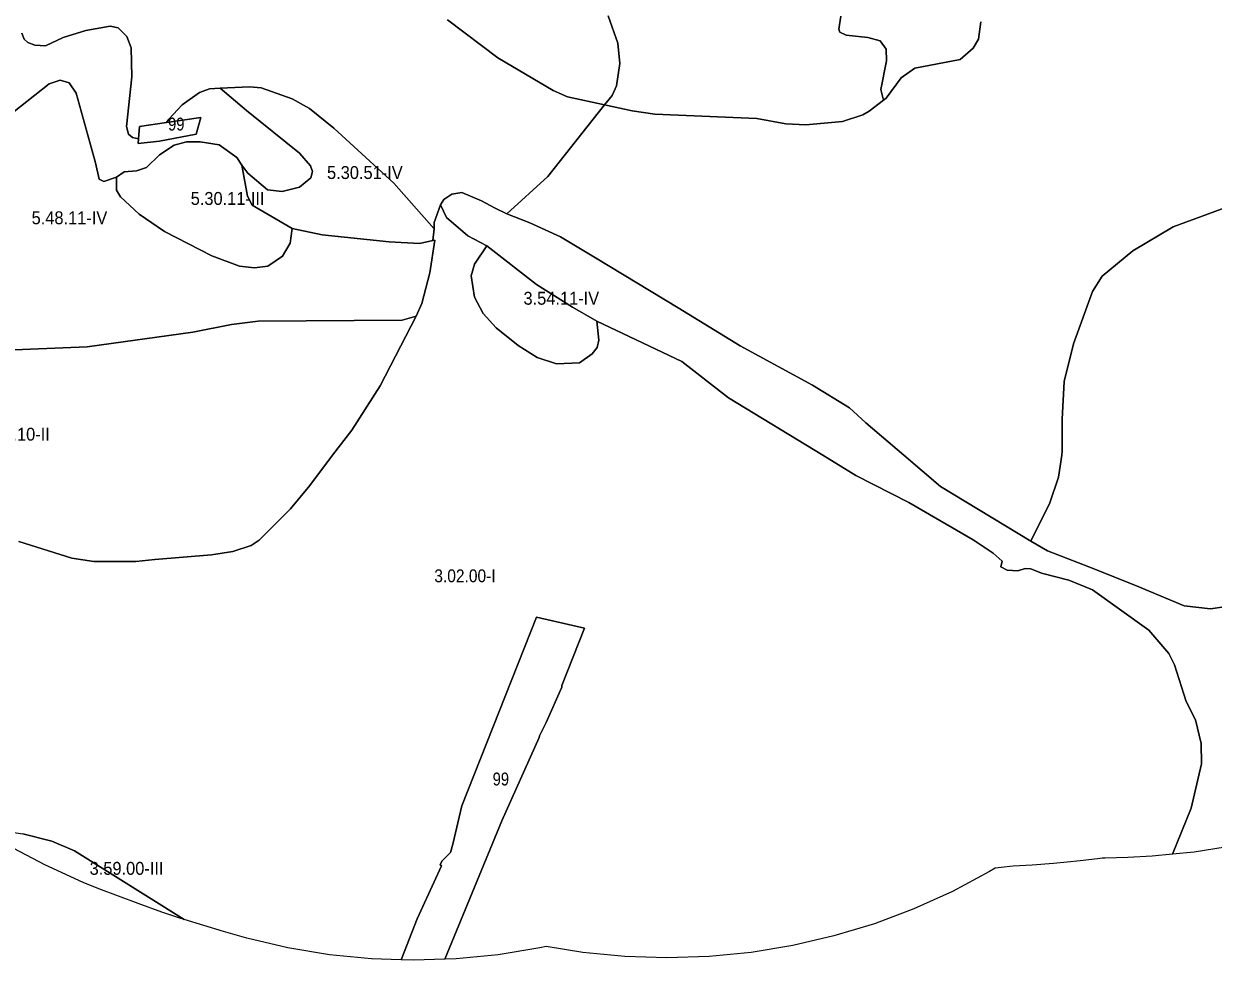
# Model space of a CAD drawing. Extents: x -591496 to -585489, y -1120610 to -1115685.
# Drawn here: x -589052 to -587209, y -1120610 to -1119158 of the extents above; entities that cross this region are included whole.
import ezdxf

# ---------------------------------------------------------------- set-up
doc = ezdxf.new("R2010")
doc.units = 0
doc.header["$LTSCALE"] = 8
doc.layers.add('40', color=7, linetype='Continuous', lineweight=25)
doc.layers.add('41', color=7, linetype='Continuous')

msp = doc.modelspace()

# ---------------------------------------------------------------- linework, layer by layer
at = {"layer": '40'}
for points in [[(-589054.5, -1119172.5), (-589051, -1119182), (-589045.5, -1119187), (-589034.5, -1119191), (-589018, -1119192), (-588990.5, -1119179.5), (-588955.5, -1119168.5), (-588917.5, -1119161.5), (-588905.5, -1119164.5), (-588892, -1119177.5), (-588885, -1119195.5), (-588884, -1119240.5), (-588892.5, -1119317), (-588889.5, -1119329), (-588883, -1119334.5), (-588873.972, -1119336.502), (-588874.5, -1119343.5), (-588841.5, -1119340), (-588784.5, -1119329), (-588777.5, -1119303.5), (-588830.496, -1119311.031), (-588827, -1119306), (-588806, -1119283.5), (-588779.5, -1119264.5), (-588764, -1119259), (-588747.5, -1119258), (-588706.5, -1119292.5), (-588624.5, -1119358.5), (-588607.5, -1119378), (-588604.5, -1119387), (-588607, -1119397), (-588624.5, -1119411.5), (-588651, -1119418), (-588674, -1119415.5), (-588704.5, -1119389.5), (-588713.5, -1119377), (-588721.5, -1119365.5), (-588749, -1119345.5), (-588778.5, -1119341), (-588799.5, -1119341), (-588818.5, -1119346), (-588841.5, -1119361), (-588861.5, -1119381), (-588877, -1119386), (-588896, -1119387.5), (-588908, -1119396), (-588927.5, -1119402.5), (-588935, -1119399), (-588940.5, -1119373.5), (-588952.5, -1119330.5), (-588970.5, -1119265.5), (-588981.5, -1119249.5), (-588995, -1119245.5), (-589012, -1119251), (-589079, -1119304)], [(-588395, -1119152), (-588317, -1119211), (-588231.5, -1119261.5), (-588209, -1119271.5), (-588151.702, -1119283.819), (-588239.5, -1119395), (-588303, -1119452.5), (-588322.5, -1119443.5), (-588342.5, -1119432.5), (-588373, -1119419.5), (-588388.5, -1119422), (-588401, -1119430.5), (-588406, -1119438.5), (-588416, -1119466), (-588416, -1119476), (-588478, -1119405), (-588571, -1119320), (-588609, -1119289.5), (-588635.5, -1119274.5), (-588684, -1119257.5), (-588702, -1119255.5), (-588747.5, -1119258), (-588764, -1119259), (-588779.5, -1119264.5), (-588806, -1119283.5), (-588827, -1119306), (-588830.496, -1119311.031), (-588872.5, -1119317), (-588873.972, -1119336.502), (-588883, -1119334.5), (-588889.5, -1119329), (-588892.5, -1119317), (-588884, -1119240.5), (-588885, -1119195.5), (-588892, -1119177.5), (-588905.5, -1119164.5), (-588917.5, -1119161.5), (-588955.5, -1119168.5), (-588990.5, -1119179.5), (-589018, -1119192), (-589034.5, -1119191), (-589045.5, -1119187), (-589051, -1119182), (-589054.5, -1119172.5)], [(-588146, -1119145.5), (-588131, -1119188), (-588128, -1119219.5), (-588133.5, -1119254), (-588140, -1119269), (-588151.702, -1119283.819), (-588209, -1119271.5), (-588231.5, -1119261.5), (-588317, -1119211), (-588395, -1119152)], [(-587171, -1119436), (-587271, -1119473), (-587333.5, -1119510), (-587381, -1119549), (-587396, -1119573), (-587425, -1119654), (-587439.5, -1119712.5), (-587442.5, -1119771), (-587442.5, -1119820.5), (-587443.448, -1119826.9), (-587448.5, -1119861), (-587462, -1119900.5), (-587491.5, -1119960), (-587631, -1119875.5), (-587687.946, -1119826.9), (-587747, -1119776.5), (-587772.5, -1119753.5), (-587829.5, -1119718), (-587941.5, -1119657.5), (-588037.5, -1119598.5), (-588166, -1119521), (-588220, -1119488.5), (-588267.5, -1119466.5), (-588303, -1119452.5), (-588239.5, -1119395), (-588151.702, -1119283.819), (-588109, -1119293), (-588074, -1119298), (-587916, -1119305), (-587871, -1119313), (-587840, -1119314.5), (-587783, -1119309.5), (-587751.5, -1119299), (-587742, -1119293.5), (-587719.491, -1119276.512), (-587715.5, -1119273.5), (-587692, -1119242), (-587671, -1119227), (-587601, -1119213.5), (-587580.5, -1119196), (-587572.5, -1119182), (-587569, -1119155)], [(-587785.5, -1119146), (-587789, -1119166.5), (-587787, -1119171), (-587777.5, -1119175.5), (-587744, -1119179.5), (-587724.5, -1119184.5), (-587715.5, -1119197.5), (-587715, -1119215.5), (-587723.5, -1119260), (-587719.491, -1119276.512), (-587742, -1119293.5), (-587751.5, -1119299), (-587783, -1119309.5), (-587840, -1119314.5), (-587871, -1119313), (-587916, -1119305), (-588074, -1119298), (-588109, -1119293), (-588151.702, -1119283.819), (-588140, -1119269), (-588133.5, -1119254), (-588128, -1119219.5), (-588131, -1119188), (-588146, -1119145.5)], [(-587569, -1119155), (-587572.5, -1119182), (-587580.5, -1119196), (-587601, -1119213.5), (-587671, -1119227), (-587692, -1119242), (-587715.5, -1119273.5), (-587719.491, -1119276.512), (-587723.5, -1119260), (-587715, -1119215.5), (-587715.5, -1119197.5), (-587724.5, -1119184.5), (-587744, -1119179.5), (-587777.5, -1119175.5), (-587787, -1119171), (-587789, -1119166.5), (-587785.5, -1119146)], [(-589079, -1119304), (-589012, -1119251), (-588995, -1119245.5), (-588981.5, -1119249.5), (-588970.5, -1119265.5), (-588952.5, -1119330.5), (-588940.5, -1119373.5), (-588935, -1119399), (-588927.5, -1119402.5), (-588908, -1119396), (-588908, -1119416), (-588901.5, -1119426.5), (-588873, -1119453), (-588833.5, -1119480), (-588760, -1119517.5), (-588717.5, -1119534), (-588694, -1119536.5), (-588673.5, -1119534), (-588650.5, -1119518.5), (-588639, -1119498), (-588635.5, -1119475.5), (-588589.5, -1119485), (-588485.5, -1119496), (-588438.5, -1119498.5), (-588418, -1119494), (-588414.5, -1119493.5), (-588422.5, -1119544), (-588435, -1119591.5), (-588443.5, -1119611), (-588465.5, -1119617.5), (-588688.5, -1119619), (-588730, -1119624), (-588789.5, -1119636), (-588953.5, -1119659), (-589167, -1119667.5)], [(-587475, -1120009.5), (-587491.5, -1120003), (-587500, -1120002.5), (-587511.5, -1120006), (-587528, -1120005), (-587537.885, -1120000), (-587535.5, -1119991), (-587549.5, -1119978.5), (-587580.5, -1119958), (-587680.5, -1119900), (-587762.5, -1119858), (-587813.556, -1119826.9), (-587959.5, -1119738), (-588032, -1119681.5), (-588163.5, -1119619), (-588201.5, -1119597.5), (-588257, -1119562), (-588334, -1119502), (-588363.5, -1119486.5), (-588396.5, -1119458.5), (-588406, -1119438.5), (-588401, -1119430.5), (-588388.5, -1119422), (-588373, -1119419.5), (-588342.5, -1119432.5), (-588322.5, -1119443.5), (-588303, -1119452.5)], [(-589059, -1119960.5), (-588977, -1119986.5), (-588943, -1119991.5), (-588878, -1119991.5), (-588848.5, -1119988.5), (-588760.5, -1119981), (-588727.5, -1119976), (-588699.5, -1119967), (-588687, -1119958.5), (-588638.5, -1119910), (-588608.5, -1119873.5), (-588573.073, -1119826.9), (-588543.5, -1119788), (-588499.5, -1119719), (-588443.5, -1119611), (-588435, -1119591.5), (-588422.5, -1119544), (-588414.5, -1119493.5), (-588418, -1119494), (-588416, -1119476), (-588416, -1119466), (-588406, -1119438.5), (-588396.5, -1119458.5), (-588363.5, -1119486.5), (-588334, -1119502)], [(-587191.5, -1120062), (-587213, -1120065), (-587253.5, -1120060.5), (-587330, -1120028.5), (-587401.421, -1120000), (-587465.5, -1119975), (-587491.5, -1119960), (-587462, -1119900.5), (-587448.5, -1119861), (-587443.448, -1119826.9), (-587442.5, -1119820.5), (-587442.5, -1119771), (-587439.5, -1119712.5), (-587425, -1119654), (-587396, -1119573), (-587381, -1119549), (-587333.5, -1119510), (-587271, -1119473), (-587171, -1119436)], [(-588303, -1119452.5), (-588267.5, -1119466.5), (-588220, -1119488.5), (-588166, -1119521), (-588037.5, -1119598.5), (-587941.5, -1119657.5), (-587829.5, -1119718), (-587772.5, -1119753.5), (-587747, -1119776.5), (-587687.946, -1119826.9), (-587631, -1119875.5), (-587491.5, -1119960), (-587465.5, -1119975), (-587401.421, -1120000), (-587330, -1120028.5), (-587253.5, -1120060.5), (-587213, -1120065), (-587191.5, -1120062)], [(-588334, -1119502), (-588353.5, -1119530.5), (-588358.5, -1119548.5), (-588353, -1119582), (-588340, -1119607), (-588319.5, -1119629.5), (-588285.5, -1119656.5), (-588256, -1119675.5), (-588226, -1119685), (-588190.5, -1119683.5), (-588171, -1119669.5), (-588163, -1119660), (-588160.5, -1119648.5), (-588163.5, -1119619), (-588032, -1119681.5), (-587959.5, -1119738), (-587813.556, -1119826.9), (-587762.5, -1119858), (-587680.5, -1119900), (-587580.5, -1119958), (-587549.5, -1119978.5), (-587535.5, -1119991), (-587537.885, -1120000), (-587528, -1120005), (-587511.5, -1120006), (-587500, -1120002.5), (-587491.5, -1120003), (-587475, -1120009.5), (-587432.5, -1120020.5), (-587395.5, -1120035.5), (-587308.5, -1120098), (-587277.5, -1120134), (-587268.5, -1120152), (-587250.5, -1120208.5), (-587236, -1120237), (-587227.5, -1120273.5), (-587227, -1120305), (-587243, -1120374), (-587271.927, -1120445.441), (-587303.277, -1120448.529), (-587341.024, -1120450.288), (-587376.084, -1120451.257), (-587380.53, -1120451.371), (-587387.973, -1120452.286), (-587414.913, -1120455.496), (-587434.983, -1120457.682), (-587456.153, -1120459.772), (-587488.997, -1120462.469), (-587518.672, -1120463.972), (-587523.681, -1120464.151), (-587532.594, -1120465.365), (-587546.494, -1120467.096), (-587555.14, -1120472.145), (-587612.851, -1120502.993), (-587672.457, -1120530), (-587733.701, -1120553.05), (-587796.321, -1120572.046), (-587860.05, -1120586.905), (-587924.614, -1120597.565), (-587989.737, -1120603.979), (-588055.14, -1120606.12), (-588120.543, -1120603.979), (-588185.666, -1120597.565), (-588242.471, -1120588.186), (-588252.16, -1120590.445), (-588316.724, -1120601.105), (-588381.847, -1120607.519), (-588399.186, -1120608.087), (-588311, -1120393.5), (-588252.891, -1120264.3), (-588252.8, -1120261.96), (-588242.433, -1120241.046), (-588217.808, -1120186.293), (-588217.71, -1120183.76), (-588182.99, -1120094.972), (-588257.036, -1120077.884), (-588372.789, -1120370.571), (-588387.07, -1120429.65), (-588390.24, -1120442.75), (-588403.41, -1120455.54), (-588405.4, -1120459.36), (-588406.57, -1120461.61), (-588404.53, -1120463.5), (-588442.069, -1120545.749), (-588467.088, -1120609.011), (-588512.653, -1120607.519), (-588577.776, -1120601.105), (-588642.34, -1120590.445), (-588706.069, -1120575.586), (-588742.065, -1120565.214), (-588803.039, -1120546.402), (-588973, -1120440), (-589008, -1120425), (-589053, -1120413.5)], [(-589167, -1119667.5), (-588953.5, -1119659), (-588789.5, -1119636), (-588730, -1119624), (-588688.5, -1119619), (-588465.5, -1119617.5), (-588443.5, -1119611), (-588499.5, -1119719), (-588543.5, -1119788), (-588573.073, -1119826.9), (-588608.5, -1119873.5), (-588638.5, -1119910), (-588687, -1119958.5), (-588699.5, -1119967), (-588727.5, -1119976), (-588760.5, -1119981), (-588848.5, -1119988.5), (-588878, -1119991.5), (-588943, -1119991.5), (-588977, -1119986.5), (-589059, -1119960.5)], [(-587190.445, -1120434.35), (-587238.154, -1120442.115), (-587271.927, -1120445.441), (-587243, -1120374), (-587227, -1120305), (-587227.5, -1120273.5), (-587236, -1120237), (-587250.5, -1120208.5), (-587268.5, -1120152), (-587277.5, -1120134), (-587308.5, -1120098), (-587395.5, -1120035.5), (-587432.5, -1120020.5), (-587475, -1120009.5)]]:
    msp.add_lwpolyline(points, dxfattribs=at)
for points in [[(-588416, -1119476), (-588418, -1119494), (-588438.5, -1119498.5), (-588485.5, -1119496), (-588589.5, -1119485), (-588635.5, -1119475.5), (-588697.5, -1119439), (-588705, -1119425), (-588713.5, -1119377), (-588704.5, -1119389.5), (-588674, -1119415.5), (-588651, -1119418), (-588624.5, -1119411.5), (-588607, -1119397), (-588604.5, -1119387), (-588607.5, -1119378), (-588624.5, -1119358.5), (-588706.5, -1119292.5), (-588747.5, -1119258), (-588702, -1119255.5), (-588684, -1119257.5), (-588635.5, -1119274.5), (-588609, -1119289.5), (-588571, -1119320), (-588478, -1119405)], [(-588873.972, -1119336.502), (-588872.5, -1119317), (-588830.496, -1119311.031), (-588777.5, -1119303.5), (-588784.5, -1119329), (-588841.5, -1119340), (-588874.5, -1119343.5)], [(-588713.5, -1119377), (-588705, -1119425), (-588697.5, -1119439), (-588635.5, -1119475.5), (-588639, -1119498), (-588650.5, -1119518.5), (-588673.5, -1119534), (-588694, -1119536.5), (-588717.5, -1119534), (-588760, -1119517.5), (-588833.5, -1119480), (-588873, -1119453), (-588901.5, -1119426.5), (-588908, -1119416), (-588908, -1119396), (-588896, -1119387.5), (-588877, -1119386), (-588861.5, -1119381), (-588841.5, -1119361), (-588818.5, -1119346), (-588799.5, -1119341), (-588778.5, -1119341), (-588749, -1119345.5), (-588721.5, -1119365.5)], [(-588163.5, -1119619), (-588160.5, -1119648.5), (-588163, -1119660), (-588171, -1119669.5), (-588190.5, -1119683.5), (-588226, -1119685), (-588256, -1119675.5), (-588285.5, -1119656.5), (-588319.5, -1119629.5), (-588340, -1119607), (-588353, -1119582), (-588358.5, -1119548.5), (-588353.5, -1119530.5), (-588334, -1119502), (-588257, -1119562), (-588201.5, -1119597.5)], [(-588399.186, -1120608.087), (-588447.25, -1120609.66), (-588467.088, -1120609.011), (-588442.069, -1120545.749), (-588404.53, -1120463.5), (-588406.57, -1120461.61), (-588405.4, -1120459.36), (-588403.41, -1120455.54), (-588390.24, -1120442.75), (-588387.07, -1120429.65), (-588372.789, -1120370.571), (-588257.036, -1120077.884), (-588182.99, -1120094.972), (-588217.71, -1120183.76), (-588217.808, -1120186.293), (-588242.433, -1120241.046), (-588252.8, -1120261.96), (-588252.891, -1120264.3), (-588311, -1120393.5)], [(-588803.039, -1120546.402), (-588811.135, -1120543.904), (-588837.759, -1120535.28), (-588874.545, -1120521.985), (-588935.115, -1120498.745), (-588959.573, -1120488.99), (-589019.179, -1120461.983), (-589076.89, -1120431.135), (-589098.173, -1120417.901), (-589103.96, -1120416.945), (-589110.384, -1120415.448), (-589105, -1120411), (-589090.5, -1120408), (-589053, -1120413.5), (-589008, -1120425), (-588973, -1120440)]]:
    msp.add_lwpolyline(points, close=True, dxfattribs=at)

# ---------------------------------------------------------------- texts
at = {"layer": '41'}
for s, width, p in [('99', 0.85, (-588828, -1119323.5)), ('5.30.51-IV', 0.95, (-588581.75, -1119398.625)), ('5.30.11-III', 0.95, (-588792.969, -1119438.75)), ('5.48.11-IV', 0.95, (-589039.438, -1119468.75)), ('3.54.11-IV', 0.95, (-588277.375, -1119593.5)), ('3.12.10-II', 0.95, (-589118.625, -1119804.25)), ('3.02.00-I', 0.9, (-588415.531, -1120023.75)), ('99', 0.85, (-588325.063, -1120338.75)), ('3.59.00-III', 0.95, (-588949.563, -1120477.25))]:
    msp.add_text(s, height=20, dxfattribs=dict(at, width=width)).set_placement(p)

doc.saveas('drawing.dxf')
